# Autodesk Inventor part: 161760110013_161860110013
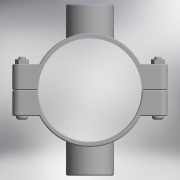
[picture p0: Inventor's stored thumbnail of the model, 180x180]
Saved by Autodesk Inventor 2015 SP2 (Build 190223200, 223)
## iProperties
Created: 2017-05
Part Number: 161760110013_161860110013
Material: Generic
Description: PLASSON DOUBLE SADDLE 110-1.1/4"
Document SubType Name: Modeling
Designer: KIM
Density: 1 g/cm^3
Appearance: Default
Author: KIM
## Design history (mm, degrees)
derived "16176.ipt"
feature "Solid1::16176.ipt"
feature "Solid2::16176.ipt"
tag "TaggingFeature1"
body "Solid1"
body "Solid2"
other parameters: "d0" = 121, "d1" = 165, "d2" = 55, "d4" = 116, "d5" = 0, "d6" = 8.25, "d7" = 165, "d8" = 0.1, "d10" = 0, "d11" = 1.1, "d20" = 1.1, "d23" = 1.1, "d36" = 13, "d37" = 10.4, "d38" = 63, "d39" = 0, "d40" = 3, "d41" = 5, "d42" = 0, "d43" = 8, "d44" = 3, "d45" = 0, "d46" = 1.1, "d52" = 38.952, "d53" = 25, "d54" = 0, "d55" = 32, "d57" = 0, "d58" = 118.8, "d60" = 0, "d62" = 13, "d63" = 10.4, "d66" = 95.2, "d67" = 182, "d68" = 50.6376, "d69" = 38.952, "d70" = 25, "d71" = 0, "d72" = 32, "d74" = 0, "d75" = 1.1, "B_" = 32, "G_" = 38.952, "A_" = 91, "L_" = 165, "L_1" = 116, "l_2" = 25
